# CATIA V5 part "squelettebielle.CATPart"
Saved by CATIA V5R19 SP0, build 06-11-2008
Part number: squelette bielle
Bounding box of the stored display mesh (mm): x 0 to 0, y 0 to 39, z -34 to -12
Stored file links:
  C:\Users\Gauthier\Documents\IFMA\IAO\TP2\squelettebielle.CATPart
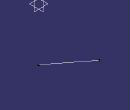
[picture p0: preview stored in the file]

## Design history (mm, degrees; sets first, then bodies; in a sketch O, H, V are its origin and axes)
Set1
  Line1: type PtPt, SecondPoint Point2, FirstPoint Point1
  Point1: stored without definition
  Point2: stored without definition
Body1 (main body)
